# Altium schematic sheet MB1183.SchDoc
size A4; Revision: C.1
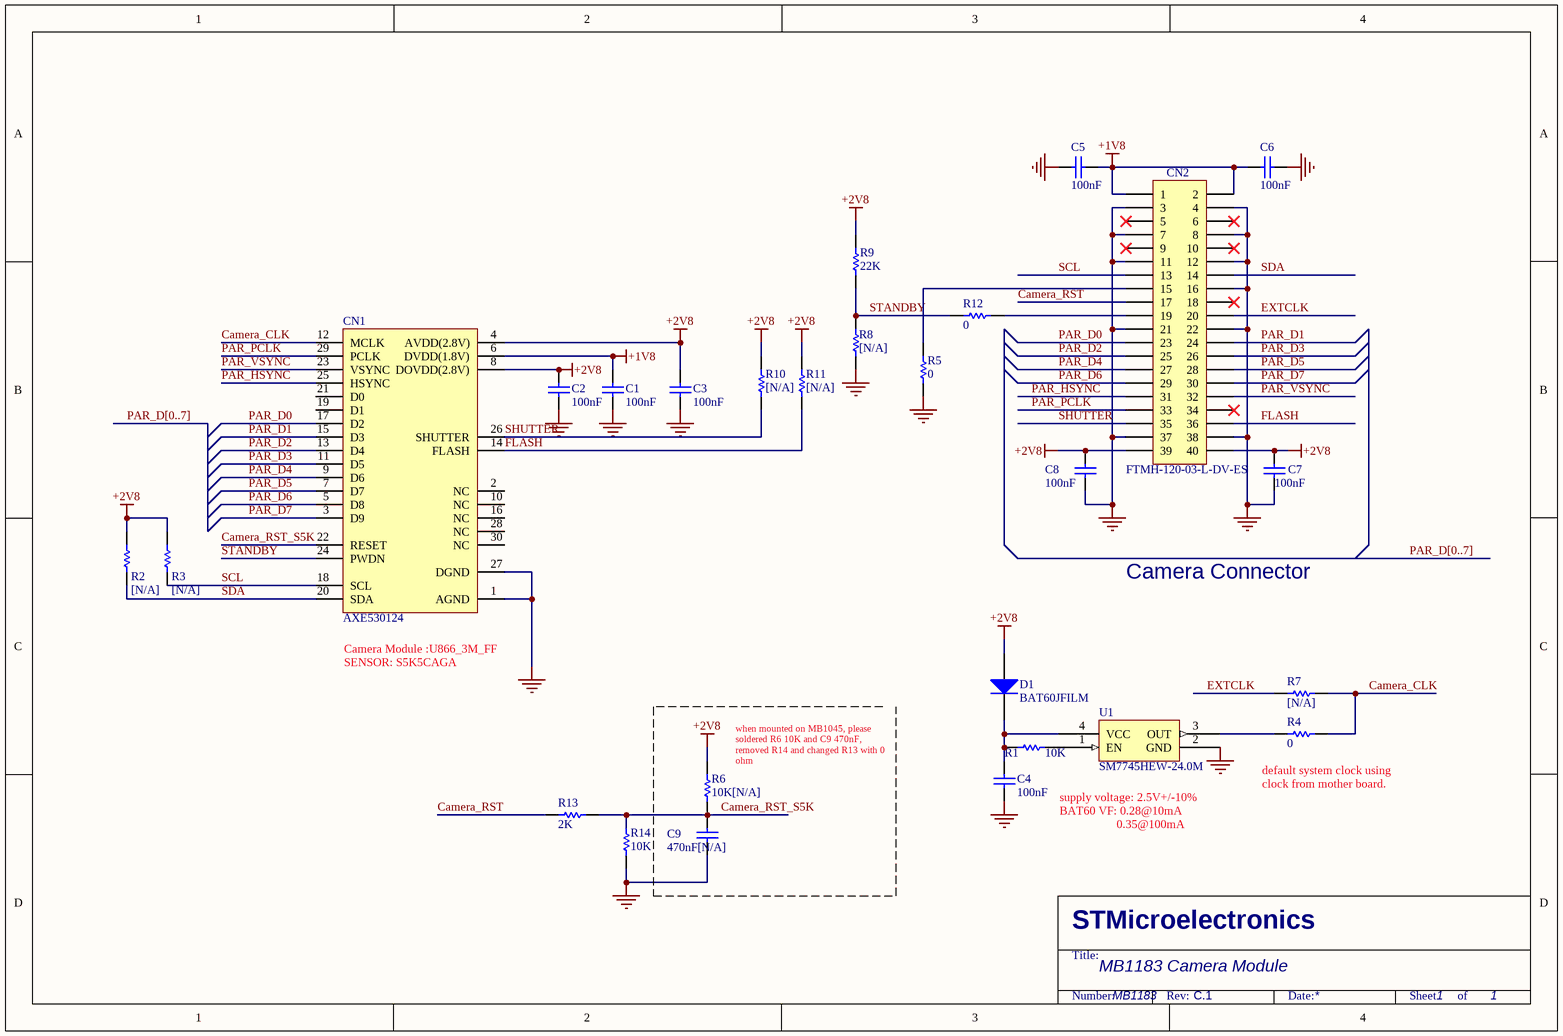
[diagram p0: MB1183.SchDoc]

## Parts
C1  100nF  [0603C]
C2  100nF  [0603C]
C3  100nF  [0603C]
C4  100nF  [0603C]
C5  100nF  [0603C]
C6  100nF  [0603C]
C7  100nF  [0603C]
C8  100nF  [0603C]
C9  470nF[N/A]  [0603C]
CN1  AXE530124  [AXE530124]
CN2  FTMH-120-03-L-DV-ES  [FTMH-120-03-L-DV-ES]
D1  BAT60JFILM  [SOD-323]
R1  10K  [0603R]
R2  [N/A]  [0603R]
R3  [N/A]  [0603R]
R4  0  [0603R]
R5  0  [0603R]
R6  10K[N/A]  [0603R]
R7  [N/A]  [0603R]
R8  [N/A]  [0603R]
R9  22K  [0603R]
R10  [N/A]  [0603R]
R11  [N/A]  [0603R]
R12  0  [0603R]
R13  2K  [0603R]
R14  10K  [0603R]
U1  SM7745HEW-24.0M  [XTAL_5X7]

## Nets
+1V8: C1.1 C5.2 C6.1 CN1.6(DVDD(1.8V)) CN2.1 CN2.2
+2V8: C2.1 C3.1 C7.1 C8.1 CN1.4(AVDD(2.8V)) CN1.8(DOVDD(2.8V)) CN2.39 CN2.40 D1.1(A) R2.1 R3.1 R6.1 R9.1 R10.1 R11.1
GND: C1.2 C2.2 C3.2 C4.2 C5.1 C6.2 C7.2 C8.2 C9.2 CN1.1(AGND) CN1.27(DGND) CN2.3 CN2.4 CN2.7 CN2.8 CN2.11 CN2.12 CN2.16 CN2.21 CN2.22 CN2.37 CN2.38 R5.2 R8.1 R14.2 U1.2(GND)
Camera_CLK: CN1.12(MCLK) R4.2 R7.2
Camera_RST: CN2.17 R13.1
Camera_RST_S5K: C9.1 CN1.22(RESET) R6.2 R13.2 R14.1
EXTCLK: CN2.20 R7.1
FLASH: CN1.14(FLASH) CN2.36 R11.2
PAR_D0: CN1.17(D2) CN2.23
PAR_D1: CN1.15(D3) CN2.24
PAR_D2: CN1.13(D4) CN2.25
PAR_D3: CN1.11(D5) CN2.26
PAR_D4: CN1.9(D6) CN2.27
PAR_D5: CN1.7(D7) CN2.28
PAR_D6: CN1.5(D8) CN2.29
PAR_D7: CN1.3(D9) CN2.30
PAR_HSYNC: CN1.25(HSYNC) CN2.31
PAR_PCLK: CN1.29(PCLK) CN2.33
PAR_VSYNC: CN1.23(VSYNC) CN2.32
SCL: CN1.18(SCL) CN2.13 R3.2
SDA: CN1.20(SDA) CN2.14 R2.2
SHUTTER: CN1.26(SHUTTER) CN2.35 R10.2
STANDBY: CN1.24(PWDN) R8.2 R9.2 R12.1
NetC4_1: C4.1 D1.2(K) R1.1 U1.4(VCC)
NetCN2_15: CN2.15 R5.1
NetCN2_19: CN2.19 R12.2
NetR1_2: R1.2 U1.1(EN)
NetR4_1: R4.1 U1.3(OUT)

Not connected (* = marked no-connect by the designer): CN1 2(NC) 10(NC) 16(NC) 19(D1) 21(D0) 28(NC) 30(NC); CN2 5* 6* 9* 10* 18* 34*

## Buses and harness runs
bus PAR_D[0..7]

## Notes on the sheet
- Camera Connector
- (near CN1) Camera Module :U866_3M_FF
  SENSOR: S5K5CAGA
- (near R6) when mounted on MB1045, please soldered R6 10K and C9 470nF, removed R14 and changed R13 with 0 ohm
- supply voltage: 2.5V+/-10%
  BAT60 VF: 0.28@10mA
  0.35@100mA
- (near R4) default system clock using clock from mother board.
- MB1183 Camera Module
- MB1183
- 1

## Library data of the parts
C1-C8 = Cap: Capacitor; Value: 10nF
C9 = Cap: Capacitor; Value: 470nF
CN1 = U866_3M_FF: CAMERA MODULE
CN2 = Header 20X2: 20*2Pins, 1mm_SMT, male
D1 = Diode: Default Diode; Code - JEDEC: DO-214-AB
R1 R3 R5 R7-R14 = Res1: Resistor; Value: 1K
R2 = Res1: Resistor 10K; Value: 1K
R4 = Res1: Resistor
R6 = Res1: Resistor; Value: 10K
U1 = SM7745HEV-50.0M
